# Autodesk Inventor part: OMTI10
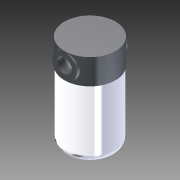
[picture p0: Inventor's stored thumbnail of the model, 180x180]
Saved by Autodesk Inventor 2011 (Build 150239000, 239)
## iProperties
Created: 2013-02
Part Number: OMTI10
Document SubType Name: Modeling
Designer: khramov
Density: 1 g/cm^3
Author: khramov
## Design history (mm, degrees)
derived "OMTI10.iam"
node "Твердое тело1"
node "T05VORI.ipt:1"
node "FRCE-034L.ipt:1"
